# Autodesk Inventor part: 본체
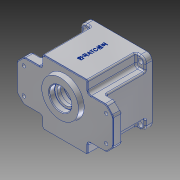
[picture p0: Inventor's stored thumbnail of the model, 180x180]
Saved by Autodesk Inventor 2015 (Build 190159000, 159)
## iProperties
Created: 2016-02
Part Number: 본체
Material: Aluminum 6061
Document SubType Name: Modeling
Designer: Administrator
Density: 2.7 g/cm^3
Appearance: Aluminum - Flat
Mass: 873.698 g
Surface Area: 761.101 cm^2
Volume: 323.592 cm^3
Author: Administrator
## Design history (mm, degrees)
sketch "Sketch1"
  geometry: L1 (47, -47)-(-47, -47); L2 (-47, -47)-(-47, 47); L3 (-47, 47)-(47, 47); L4 (47, 47)-(47, -47); L5 (47, -47)-(-47, 47); L6 (-47, -47)-(47, 47); 1 further point
  constraints: 12 end point, 2 midpoint, 2 parallel, 1 horizontal, 1 perpendicular
  dimensions: "d0" = 94 distance of L2.end L3.end; "d1" = 94 distance of L1.end L2.end
extrude "Extrusion1" new body sketch "Sketch1" distance "d2" = 10; taper "d3" = 0 deg
sketch "Sketch2"
  geometry: L1 (33, -47)-(-33, -47); L2 (-33, -47)-(-33, 47); L3 (-33, 47)-(33, 47); L4 (33, 47)-(33, -47); L5 (33, -47)-(-33, 47); L6 (-33, -47)-(33, 47); L7 (47, 30)-(-47, 30); L8 (-47, 30)-(-47, -30); L9 (-47, -30)-(47, -30); L10 (47, -30)-(47, 30); L11 (47, 30)-(-47, -30); L12 (-47, 30)-(47, -30); 1 further point
  constraints: 24 end point, 4 midpoint, 4 parallel, 2 horizontal, 2 perpendicular
  dimensions: "d4" = 66 distance of L2.end L3.end; "d5" = 94 distance of L1.end L2.end; "d6" = 94 distance of L9.end L8.end; "d7" = 60 distance of L9.end L7.start
extrude "Extrusion2" join sketch "Sketch2" distance "d8" = 57; taper "d9" = 0 deg
sketch "Sketch3"
  geometry: L1 (70, -30)-(-70, -30); L2 (-70, -30)-(-70, 30); L3 (-70, 30)-(70, 30); L4 (70, 30)-(70, -30); L5 (70, -30)-(-70, 30); L6 (-70, -30)-(70, 30); L7 (33, -47)-(-33, -47); L8 (-33, -47)-(-33, 47); L9 (-33, 47)-(33, 47); L10 (33, 47)-(33, -47); L11 (33, -47)-(-33, 47); L12 (-33, -47)-(33, 47); 1 further point
  constraints: 24 end point, 4 midpoint, 4 parallel, 2 horizontal, 2 perpendicular
  dimensions: "d10" = 140 distance of L2.end L3.end; "d11" = 60 distance of L1.end L2.end; "d12" = 66 distance of L8.end L9.end; "d13" = 94 distance of L7.end L8.end
extrude "Extrusion3" join sketch "Sketch3" distance "d14" = 13; taper "d15" = 0 deg
sketch "Sketch4"
  geometry: C1 r 43 at (0, 0); 1 further point
  constraints: 1 centre point, 1 coincident
  dimensions: "d16" = 86 diameter of C1
extrude "Extrusion4" cut sketch "Sketch4" distance "d17" = 9; taper "d18" = 0 deg
hole "Hole1" diameter "d21" = 80; stored, may be unused: countersink angle "d25" = 90 deg, drill point angle "d27" = 0 deg; dims "d19" = 10, "d20" = 10, "d22" = 6, "d23" = 4, "d24" = 2, "d26" = 62
chamfer "Chamfer1" distance "d28" = 10; stored, may be unused: second distance "d29" = 2, angle "d30" = 45 deg
sketch "Sketch5"
  geometry: C1 r 28 at (0, -11); 1 further point
  constraints: 1 centre point, 1 vertical alignment
  dimensions: "d31" = 56 diameter of C1; "d32" = 11 distance of C1.centre point (0, 0)
extrude "Extrusion5" join sketch "Sketch5" distance "d33" = 7; taper "d34" = -10 deg
hole "Hole2" diameter "d37" = 32; stored, may be unused: countersink angle "d41" = 90 deg, drill point angle "d43" = 0 deg; dims "d35" = 10, "d36" = 10, "d38" = 6, "d39" = 4, "d40" = 2, "d42" = 8
hole "Hole3" diameter "d46" = 25; stored, may be unused: countersink angle "d50" = 90 deg, drill point angle "d52" = 0 deg; dims "d44" = 10, "d45" = 10, "d47" = 6, "d48" = 4, "d49" = 2, "d51" = 5
hole "Hole4" diameter "d55" = 35; stored, may be unused: countersink angle "d59" = 90 deg, drill point angle "d61" = 0 deg; dims "d53" = 10, "d54" = 10, "d56" = 6, "d57" = 4, "d58" = 2, "d60" = 10
sketch "Sketch6"
  geometry: C1 r 21 at (0, -11); A1 r 17.5 centre (0, -11) between (-4.864, 5.81) and (4.864, 5.81) reference; A2 r 15 centre (0, 20) between (4.864, 5.81) and (-4.864, 5.81); 1 further point
  constraints: 4 point on circle, 2 centre point, 1 coincident, 1 vertical alignment
  dimensions: "d62" = 21 radius of C1; "d63" = 15 radius of A2; "d64" = 20 distance of point (0, 0) A2.centre
extrude "Extrusion6" join sketch "Sketch6" distance "d65" = 7; taper "d66" = 0 deg
hole "Hole5" diameter "d69" = 22; stored, may be unused: countersink angle "d73" = 90 deg, drill point angle "d75" = 0 deg; dims "d67" = 10, "d68" = 10, "d70" = 6, "d71" = 4, "d72" = 2, "d74" = 7
hole "Hole6" diameter "d78" = 19; stored, may be unused: countersink angle "d82" = 90 deg, drill point angle "d84" = 0 deg; dims "d76" = 10, "d77" = 10, "d79" = 6, "d80" = 4, "d81" = 2, "d83" = 1
sketch "Sketch7"
  geometry: L1 (39.799, 4)-(35.777, 4); L2 (-35.777, 4)-(-39.799, 4); L3 (39.799, -4)-(35.777, -4); L4 (-35.777, -4)-(-39.799, -4); A1 r 36 centre (0, 0) between (36, 0) and (-36, 0); A2 r 4 centre (36, 0) between (36, 4) and (36, -4); A3 r 4 centre (-36, 0) between (-36, -4) and (-36, 4); A4 r 40 centre (0, 0) between (39.799, -4) and (39.799, 4) reference; 1 further point
  constraints: 14 point on circle, 8 end point, 4 horizontal, 4 point on line, 4 tangent, 3 centre point, 2 horizontal alignment, 1 coincident
  dimensions: "d85" = 36 radius of A1; "d86" = 4 radius of A2; "d87" = 4 radius of A3
extrude "Extrusion7" join sketch "Sketch7" stored distance "d88" = 7; taper "d89" = 0 deg
fillet "Fillet1" dims "d90" = 3.5
sketch "Sketch9"
  geometry: L1 (60, -19)-(-60, -19); L2 (-60, -19)-(-60, 19); L3 (-60, 19)-(60, 19); L4 (60, 19)-(60, -19); L5 (60, -19)-(-60, 19); L6 (-60, -19)-(60, 19); 5 further points
  constraints: 12 end point, 4 coincident, 2 midpoint, 2 parallel, 1 horizontal, 1 perpendicular
  dimensions: "d93" = 120 distance of L2.end L3.end; "d94" = 38 distance of L1.end L2.end
hole "Hole7" sketch "Sketch9" at (-60, 19), (-60, -19), (60, -19), (60, 19) diameter "d95" = 5; stored, may be unused: countersink angle "d99" = 90 deg, drill point angle "d101" = 0 deg; dims "d96" = 6, "d97" = 9, "d98" = 4, "d100" = 13
sketch "Sketch10"
  geometry: L1 (60, 30)-(70, 20) reference; L2 (60, 30)-(33, 30) reference; L3 (33, 30)-(33, 47) reference; L4 (33, 47)-(-33, 47) reference; L5 (-33, 47)-(-33, 30) reference; L6 (-33, 30)-(-60, 30) reference; L7 (-70, 20)-(-60, 30) reference; L8 (-70, 20)-(-70, -20) reference; L9 (-60, -30)-(-70, -20) reference; L10 (-60, -30)-(-33, -30) reference; L11 (-33, -30)-(-33, -47) reference; L12 (-33, -47)-(33, -47) reference; L13 (33, -47)-(33, -30) reference; L14 (33, -30)-(60, -30) reference; L15 (70, -20)-(60, -30) reference; L16 (70, -20)-(70, 20) reference; L17 (59.586, -29)-(32, -29); L18 (32, -29)-(32, -46); L19 (32, -46)-(-32, -46); L20 (-32, -46)-(-32, -29); L21 (-32, -29)-(-59.586, -29); L22 (-59.586, -29)-(-69, -19.586); L23 (-69, -19.586)-(-69, 19.586); L24 (-69, 19.586)-(-59.586, 29); L25 (-59.586, 29)-(-32, 29); L26 (-32, 29)-(-32, 46); L27 (-32, 46)-(32, 46); L28 (32, 46)-(32, 29); L29 (32, 29)-(59.586, 29); L30 (59.586, 29)-(69, 19.586); L31 (69, 19.586)-(69, -19.586); L32 (69, -19.586)-(59.586, -29); C1 r 2.5 at (-60, -19) reference; C2 r 2.5 at (60, 19) reference; C3 r 2.5 at (60, -19) reference; C4 r 2.5 at (-60, 19) reference; C5 r 28 at (0, -11) reference; 1 further point
  constraints: 32 end point, 15 other
  dimensions: "d102" = 1 distance between parallel lines of L14 L17
extrude "Extrusion8" cut sketch "Sketch10" distance "d103" = 1; taper "d104" = 0 deg
fillet "Fillet2" dims "d105" = 5
fillet "Fillet3" dims "d106" = 8
fillet "Fillet4" dims "d107" = 3
sketch "Sketch11"
  geometry: L1 (72, -79)-(-6, -79) reference; 3 further points
  constraints: 1 midpoint, 1 vertical alignment, 1 other
  dimensions: "d132" = 40 distance of point (33, -79) point (33, -39)
emboss "Emboss1" sketch "Sketch11" dims "d0" = 94, "d1" = 94, "d108" = 0.5, "d109" = 0
fillet "Fillet5" dims "d110" = 2
fillet "Fillet6" dims "d111" = 2
fillet "Fillet7" dims "d112" = 0.3
chamfer "Chamfer2" distance "d113" = 1; stored, may be unused: second distance "d114" = 2, angle "d115" = 45 deg
sketch "Sketch12"
  geometry: L1 (-40, 40)-(40, 40); L2 (40, 40)-(40, -40); L3 (40, -40)-(-40, -40); L4 (-40, -40)-(-40, 40); L5 (-40, 40)-(40, -40); L6 (40, 40)-(-40, -40); 5 further points
  constraints: 12 end point, 3 coincident, 2 midpoint, 2 parallel, 1 horizontal, 1 perpendicular
  dimensions: "d116" = 80 distance of L2.end L3.end; "d117" = 80 distance of L1.end L2.end
hole "Hole8" sketch "Sketch12" at (40, -40), (40, 40), (-40, 40), (-40, -40) diameter "d118" = 7; stored, may be unused: countersink angle "d122" = 90 deg, drill point angle "d124" = 0 deg; dims "d119" = 6, "d120" = 9, "d121" = 4, "d123" = 13
sketch "Sketch13"
  geometry: A1 r 4 centre (-36, 0) between (-35.778, -3.994) and (-35.778, 3.994) reference; A2 r 4 centre (36, 0) between (35.778, 3.994) and (35.778, -3.994) reference; 3 further points
  constraints: 2 coincident
hole "Hole9" sketch "Sketch13" at (-36, 0), (36, 0) diameter "d125" = 3.242; stored, may be unused: countersink angle "d129" = 90 deg, drill point angle "d131" = 118 deg; dims "d126" = 7, "d127" = 9, "d128" = 4, "d130" = 9
body "Solid1"
node "Projected Loop1"
